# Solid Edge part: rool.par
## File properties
Author: Argu
Template: Iso Part.par
Last saved by: Argu
Revision: 8
Application: Solid Edge
Accuracy: 0,990
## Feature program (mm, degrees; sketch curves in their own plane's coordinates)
sketch for "unnamed Protrusion 1" plane through (0, 0, 0) normal (0, -1, 0) x-axis (1, 0, 0)
  circle centre (0, 0) radius 1.5
extrude "unnamed Protrusion 1" add finite 60 along -normal
swept protrusion "SweptProtrusion_4"
sketch for "unnamed RevolvedProtrusion 1" plane through (0, 0, 0) normal (0, -1, 0) x-axis (1, 0, 0)
  line (0, 1.4974) -> (0, -1.5)
revolve "unnamed RevolvedProtrusion 1" add finite 360 deg
fillet "Round_4" radius 0.25
fillet "Round_5" radius 0.25
fillet "Round_6" radius 0.25
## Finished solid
Body 1: sheet body, 3 faces, 10 edges, 8 vertices.
  Faces by surface: plane 2, cylinder 1
  Edges by curve: line 8, circle 2
Body 2: sheet body, 5 faces, 16 edges, 12 vertices.
  Faces by surface: plane 3, cylinder 2
  Edges by curve: line 12, circle 4
Body 3: solid body, 20 faces, 32 edges, 14 vertices.
  Faces by surface: torus 6, plane 5, blend 3, cylinder 3, spline 2, sphere 1
  Edges by curve: intersection 17, circle 15
Bounding box of the edges (mm; curved faces can reach further): 150.000 x 78.440 x 150.000, from (-75, -18.4397, -79) to (75, 60, 71).
Cylindrical faces by radius (mm): R0.75 x2, R1.5 x1, R3.5 x2, R3.5026 x1
Toroidal faces (ring radius, tube radius in mm): R0.5 r0.25 x2, R3.5 r0.75 x3, R3.5026 r0.75 x1
Spherical faces by radius (mm): R1.4987 x1
Planar faces by outward normal: +y 1, -x 2, -y 2
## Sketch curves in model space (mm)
arc centre (0, 0, -0.0013) radius 1.4987 from (0, 0, 1.4974) through (1.498, 0, -0.0457) to (0, 0, -1.5)
line (0, 0, 1.4974) -> (0, 0, -1.5)
circle centre (-8, -6, -4) radius 0.75
line (-3.5, -6, -4) -> (-8, -6, -4)
arc centre (-3.5, -2.5, -4) radius 3.5 from (0, -2.5, -4) through (-1.0982, -5.0458, -4) to (-3.5, -6, -4)
line (0, 0, -4) -> (0, 3.6783, -4)
line (0, 0, -4) -> (0, -2.5, -4)
line (0, -3.5026, 4) -> (0, -18.4397, 4)
arc centre (0, -3.5026, 0.4974) radius 3.5026 from (0, 0, 0.4974) through (0, -1.099, 3.0451) to (0, -3.5026, 4)
line (0, -3.5, -4) -> (0, -18.4397, -4)
arc centre (0, -3.5, -0.5) radius 3.5 from (0, 0, -0.5) through (0, -1.0982, -3.0458) to (0, -3.5, -4)
line (0, 0, 0) -> (0, 0, -0.5)
line (0, 0, 0) -> (0, 0, 0.4974)
circle centre (0, 0, 0) radius 1.5
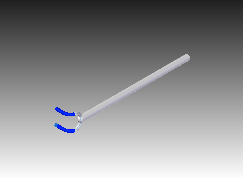
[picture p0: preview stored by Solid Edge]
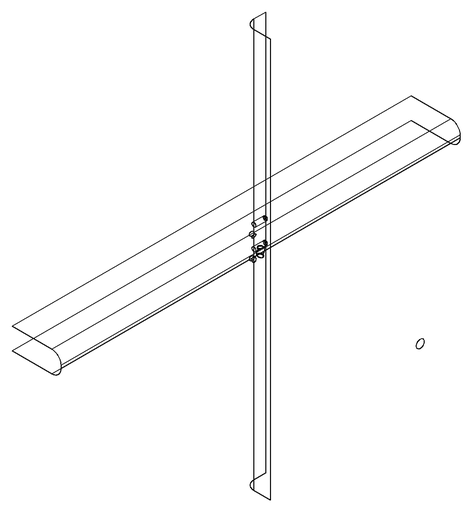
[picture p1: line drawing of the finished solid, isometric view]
